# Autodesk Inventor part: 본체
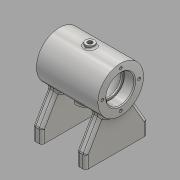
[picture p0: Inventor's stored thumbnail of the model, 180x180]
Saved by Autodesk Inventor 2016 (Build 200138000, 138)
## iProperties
Created: 2018-05
Part Number: 본체
Material: 알루미늄 6061
Document SubType Name: Modeling
Designer: Administrator
Density: 2.7 g/cm^3
Appearance: 알루미늄 - 평지
Mass: 317.681 g
Surface Area: 375.828 cm^2
Volume: 117.66 cm^3
Author: Administrator
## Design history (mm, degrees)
sketch "스케치1"
  geometry: L1 (-20, -35)-(-30, -35); L2 (-30, -35)-(-30, 35); L3 (-30, 35)-(-20, 35); L4 (-20, 35)-(-20, -35); L5 (-42, 0)-(42, 0) reference; L6 (0, -49)-(0, 49) reference; L7 (20, -35)-(30, -35); L8 (30, -35)-(30, 35); L9 (30, 35)-(20, 35); L10 (20, 35)-(20, -35); 1 further point
  constraints: 16 end point, 4 parallel, 2 horizontal, 2 perpendicular, 5 other
  dimensions: "d0" = 10 distance of L2.end L3.end; "d1" = 60 distance between parallel lines of L2 L8; "d2" = 70 distance of L9.end L7.start
extrude "돌출1" new body sketch "스케치1" distance "d3" = 15; taper "d4" = 0 deg
sketch "스케치2"
  geometry: L1 (36.295, 65)-(-44.666, 65); L2 (35, 65)-(-35, 65); L3 (-35, 65)-(-35, 91); L4 (-35, 91)-(35, 91); L5 (35, 91)-(35, 65); L6 (35, 65)-(23, 65); L7 (23, 65)-(23, 81); L8 (23, 81)-(35, 81); L9 (35, 81)-(35, 65); L10 (23, 65)-(21, 65); L11 (21, 65)-(21, 79); L12 (21, 79)-(23, 79); L13 (23, 79)-(23, 65); L14 (21, 65)-(-21, 65); L15 (-21, 65)-(-21, 86); L16 (-21, 86)-(21, 86); L17 (21, 86)-(21, 65); L18 (-21, 65)-(-23, 65); L19 (-23, 65)-(-23, 79); L20 (-23, 79)-(-21, 79); L21 (-21, 79)-(-21, 65); L22 (-23, 65)-(-35, 65); L23 (-35, 65)-(-35, 81); L24 (-35, 81)-(-23, 81); L25 (-23, 81)-(-23, 65); 2 further points
  constraints: 50 end point, 12 parallel, 7 horizontal, 6 perpendicular, 1 midpoint, 1 point on line, 1 vertical alignment
  dimensions: "d5" = 65 distance from line of point (0, 0) L1; "d6" = 70 distance of L3.end L4.end; "d7" = 26 distance of L2.end L3.end; "d8" = 12 distance of L7.end L8.end; "d9" = 16 distance of L6.end L7.end; "d10" = 2 distance of L11.end L12.end; "d11" = 14 distance of L10.end L11.end; "d12" = 42 distance of L15.end L16.end; "d13" = 21 distance of L14.end L15.end; "d14" = 2 distance of L19.end L20.end; "d15" = 14 distance of L18.end L19.end; "d16" = 12 distance of L23.end L24.end; "d17" = 16 distance of L22.end L23.end
revolve "회전1" sketch "스케치2" stored, may be unused: angle "d18" = 90 deg
sketch "스케치3"
  geometry: L1 (-30, -35)-(-30, 35) reference; L2 (-20, 35)-(-20, -35) reference; L3 (-30, -3)-(-20, -3); L4 (-20, -3)-(-20, 3); L5 (-20, 3)-(-30, 3); L6 (-30, 3)-(-30, -3); L7 (30, -35)-(30, 35) reference; L8 (20, 35)-(20, -35) reference; L9 (30, -3)-(20, -3); L10 (20, -3)-(20, 3); L11 (20, 3)-(30, 3); L12 (30, 3)-(30, -3); 4 further points
  constraints: 16 end point, 4 parallel, 4 point on line, 3 horizontal alignment, 3 midpoint, 2 horizontal, 2 perpendicular
  dimensions: "d19" = 6 distance between parallel lines of L9 L11; "d20" = 6 distance between parallel lines of L5 L3
extrude "돌출2" join sketch "스케치3" stored distance "d21" = 0; taper "d22" = 0 deg
node "작업 평면1"
sketch "스케치6"
  geometry: L1 (-15, 32)-(-15, 0) reference; L2 (-15, 0)-(-47.81, 18.943); L3 (0, 0)-(-15, 0) reference; 1 further point
  constraints: 2 end point
  dimensions: "d23" = 30 deg angle of L3 L2
feature "리브1" sketch "스케치6" dims "d24" = 1, "d25" = 10, "d26" = 0, "d27" = 0, "d28" = 1, "d29" = 1
node "작업 평면2"
sketch "스케치7"
  geometry: C1 r 5 at (0, 0); 1 further point
  constraints: 1 centre point, 1 coincident
  dimensions: "d31" = 10 diameter of C1
extrude "돌출3" join sketch "스케치7" stored distance "d32" = 15; taper "d33" = 0 deg
node "작업 평면3"
sketch "스케치8"
  geometry: L1 (-35, 26)-(35, 26) reference; L2 (-35, -26)-(-35, 26) reference; 2 further points
  constraints: 1 other
  dimensions: "d34" = 26 distance from line of L1 point (0, 0); "d35" = 35 distance from line of L2 point (0, 0)
feature "엠보싱1" sketch "스케치8" dims "d0" = 10, "d1" = 60, "d2" = 70, "d5" = 65, "d6" = 70, "d7" = 26, "d8" = 12, "d9" = 16, "d10" = 2, "d11" = 14, "d12" = 42, "d13" = 21, "d14" = 2, "d15" = 14, "d16" = 12, "d17" = 16, "d36" = 0.5, "d37" = 0
sketch "스케치9"
  geometry: L1 (-13.564, 45.276)-(-15.557, 39.801); L2 (-15.557, 39.801)-(-9.919, 37.749); L3 (-9.919, 37.749)-(0, 65); L4 (0, -18.8)-(0, 112.8) reference; L5 (-13.564, 45.276)-(-7.926, 43.224); C1 r 21 at (0, 65) reference; 1 further point
  constraints: 8 end point, 2 perpendicular, 1 parallel, 1 point on line
  dimensions: "d38" = 20 deg angle of L4 L3; "d39" = 6 distance between parallel lines of L3 L1; "d40" = 29 distance from line of L3.end L2; "d41" = 5.82629 distance between parallel lines of L2 L5
revolve "회전2" sketch "스케치9" stored, may be unused: angle "d42" = 90 deg
sketch "스케치10"
  geometry: C1 r 16 at (0, 0) reference; 2 further points
  constraints: 1 horizontal alignment
  dimensions: "d43" = 21 distance of C1.centre point (-21, 0)
hole "구멍1" sketch "스케치10" at (-21, 0) diameter "d44" = 3.242; stored, may be unused: countersink angle "d48" = 90 deg, drill point angle "d50" = 118 deg; dims "d45" = 8, "d46" = 4, "d47" = 2, "d49" = 10
hole "구멍2" diameter "d56" = 5.188; stored, may be unused: countersink angle "d60" = 90 deg, drill point angle "d62" = 118 deg; dims "d54" = 10, "d55" = 10, "d57" = 12, "d58" = 4, "d59" = 2, "d61" = 16
hole "구멍3" diameter "d65" = 5.188; stored, may be unused: countersink angle "d69" = 90 deg, drill point angle "d71" = 118 deg; dims "d63" = 10, "d64" = 10, "d66" = 12, "d67" = 4, "d68" = 2, "d70" = 16
sketch "스케치11"
  geometry: L1 (20, -35)-(30, -35) reference; L2 (30, 35)-(20, 35) reference; 5 further points
  constraints: 2 midpoint, 2 vertical alignment
  dimensions: "d72" = 40 distance of point (25, 20) point (25, -20); "d73" = 20 vertical distance of point (25, -20) point (0, 0)
hole "구멍4" sketch "스케치11" at (25, -20), (25, 20) diameter "d74" = 4.134; stored, may be unused: countersink angle "d78" = 90 deg, drill point angle "d80" = 118 deg; dims "d75" = 8, "d76" = 4, "d77" = 2, "d79" = 10
chamfer "모따기1" distance "d81" = 1; stored, may be unused: second distance "d82" = 2, angle "d83" = 45 deg
fillet "모깎기1" dims "d84" = 2
fillet "모깎기2" dims "d85" = 0.3
fillet "모깎기3" dims "d86" = 3
fillet "모깎기4" dims "d87" = 3
fillet "모깎기5" dims "d88" = 3
fillet "모깎기6" dims "d89" = 3
sketch "스케치12"
  geometry: L1 (65, 0)-(-38.669, 0); L2 (-38.669, 0)-(-38.669, 53.512); L3 (-38.669, 53.512)-(65, 53.512); L4 (65, 53.512)-(65, 0)
  constraints: 8 end point, 2 parallel, 1 horizontal, 1 perpendicular
extrude "돌출4" cut sketch "스케치12" stored distance "d90" = 0; taper "d91" = 0 deg
node "솔리드1"
mirror "대칭1"
mirror "대칭2"
pattern_circular "원형 패턴1" dims angle "d52" = 360 deg
mirror "대칭3"
mirror "대칭4"
other parameters: "d30" = 94
